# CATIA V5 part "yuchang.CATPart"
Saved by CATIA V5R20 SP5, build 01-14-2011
Part number: yuchang
Material "Iron": density 7870 kg/m3, Young's modulus 2.11e+11 Pa, Poisson ratio 0.291, thermal expansion 1.21e-05 1/K
Material "DS Marble": density 2770 kg/m3, Young's modulus 6e+10 Pa, Poisson ratio 0.27
Material "Dark Oak": density 769 kg/m3, Young's modulus 1.23e+10 Pa
Material "Walnut": density 609 kg/m3, Young's modulus 1.16e+10 Pa
Bounding box of the stored display mesh (mm): x -84.274 to 26, y -5.803 to 5.803, z -3.058 to 3.058
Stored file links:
  F:\yuchang.CATPart
  D:\CATIA V5 R20 WIN64\CATIA V5 R20\win_b64\startup\materials\Catalog.CATMaterial
  D:\CATIA V5 R20 WIN64\CATIA V5 R20\win_b64\startup\materials\dark_oak.jpg
  D:\CATIA V5 R20 WIN64\CATIA V5 R20\win_b64\startup\materials\walnut.jpg
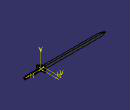
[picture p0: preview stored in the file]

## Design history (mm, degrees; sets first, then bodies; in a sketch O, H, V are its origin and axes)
Body1 (main body), material "Dark Oak"
  Sketch1 on xy-plane, origin (0, 0, 0), H (1, 0, 0), V (0, 1, 0)
    point P1 (4, 0)
    line L1 (4, 0) -> (4, 5.8034)
    point P2 (4, 5.8034)
    arc A1 centre (4.0286, 3.9101) radius 1.8935 from (4, 5.8034) to (2.1616, 4.2259) ccw
    point P4 (2.1616, 4.2259)
    arc A2 centre (2.9922, 1.1934) radius 3.1442 from (2.1616, 4.2259) to (0, 2.1592) ccw
    point P6 (0, 2.1592)
    line L2 (0, 2.1592) -> (-1.8753, 0)
    point P7 (-1.8753, 0)
    axis line L3 (-3.4574, 0) -> (9.2536, 0)
    point P8 (-3.4574, 0)
    point P10 (-1.8753, 0)
    point P11 (0, -2.1592)
    line L4 (0, -2.1592) -> (-1.8753, 0)
    point P12 (2.1616, -4.2259)
    arc A3 centre (2.9922, -1.1934) radius 3.1442 from (2.1616, -4.2259) to (0, -2.1592) cw
    point P14 (4, -5.8034)
    arc A4 centre (4.0286, -3.9101) radius 1.8935 from (4, -5.8034) to (2.1616, -4.2259) cw
    point P16 (4, 0)
    line L5 (4, 0) -> (4, -5.8034)
    distance L1 V = 4
    coincidence: P1 H, P6 V, P8 H, P1 P16, P7 P10
    vertical: L1 V
    tangency: L2 A1
    horizontal: L3 H
    symmetry: P7 P10 L3, P6 P11 L3, L2 L4 L3, P4 P12 L3, A2 A3 L3, P2 P14 L3, A1 A4 L3, P1 P16 L3, L1 L5 L3
  Pad1: profile Sketch1, direction (0, 0, 1), length 2, mirrored extent
  Sketch2 on xy-plane, origin (0, 0, 0), H (1, 0, 0), V (0, 1, 0)
    point P1 (4, 0)
    distance P1 V = 4
    coincidence: P1 H
  Plane1: type Angle, RefPlane xy-plane, Direction Y axis, Angle 90
  Plane2: type Offset, RefPlane Plane1, Offset 4
  Sketch3 on Plane2, origin (4, 0, 0), H (0, 1, 0), V (0, 0, 1)
    axis line L1 (-6.2412, 0) -> (7.4049, 0)
    point P1 (-6.2412, 0)
    coincidence: P1 H
    horizontal: L1 H
  Body2, material "DS Marble"
    Sketch4 on Plane2, origin (4, 0, 0), H (0, 1, 0), V (0, 0, 1)
      arc A1 centre (0, 0) radius 3.2 from (3.2, 0) to (-3.2, 0) ccw
      axis line L1 (-6.2184, 0) -> (7.2498, 0)
      point P1 (-6.2184, 0)
      point P3 (-3.2, 0)
      point P4 (3.2, 0)
      radius A1 = 3.2
      coincidence: P1 H, L1 P3, L1 P4
      horizontal: L1 H
    Shaft1: profile Sketch4, axis Sketch4.L1, angle 180
  Assemble1: tool Body2
Body3, material "Walnut"
  Sketch5 on Plane2, origin (4, 0, 0), H (0, 1, 0), V (0, 0, 1)
    circle A1 centre (0, 0) radius 1.7208
  Pad2: profile Sketch5, direction (1, 0, 0), length 22
  Body4
    Plane3: type Offset, RefPlane xy-plane, Offset 1.2
    Sketch6 on Plane3, origin (0, 0, 1.2), H (1, 0, 0), V (0, 1, 0)
      line L1 (4.0451, 2.1516) -> (23.6416, 2.1516)
      line L2 (23.6416, 2.1516) -> (23.6416, -2.3796)
      line L3 (23.6416, -2.3796) -> (4.0451, -2.3796)
      line L4 (4.0451, -2.3796) -> (4.0451, 2.1516)
      horizontal: L1 H, L3 H
      vertical: L2 V, L4 V
    Pad3: profile Sketch6, direction (0, 0, 1), length 4
    Mirror1: of Pad3, about xy-plane
  Remove1: tool Body4
  Body5
    Sketch7 on face of Pad3 from Sketch6.L4, origin (4.0451, 0, 0), H (0, 1, 0), V (0, 0, 1)
      circle A1 centre (0, 1.216) radius 0.1
      point P1 (0, 1.216)
      radius A1 = 0.1
      coincidence: P1 V
    Pad4: profile Sketch7, direction (1, 0, 0), length 20
    Mirror2: of Pad4, about xy-plane
  Assemble2: tool Body5
Body6, material "Iron"
  Plane4: type Angle, RefPlane xy-plane, Direction X axis, Angle 7.5
  Sketch8 on Plane2, origin (4, 0, 0), H (0, 1, 0), V (0, 0, 1)
    line L1 (-2.9997, 0) -> (0, 0.5)
    point P1 (-2.9997, 0)
    point P2 (0, 0.5)
    line L2 (0, 0.5) -> (2.9997, 0)
    line L3 (2.9997, 0) -> (0, -0.5)
    line L4 (0, -0.5) -> (-2.9997, 0)
    point P3 (2.9997, 0)
    coincidence: P1 H, P2 V, P3 H
    parallelism: L4 L2, L1 L3
  Pad5: profile Sketch8, direction (-1, 0, 0), length 90
  Plane5: type Angle, RefPlane xy-plane, Direction Y axis, Angle -40
  Sketch9 on xy-plane, origin (0, 0, 0), H (1, 0, 0), V (0, 1, 0)
    axis line L1 (-91.9939, 0) -> (33.05, 0)
    point P1 (-91.9939, 0)
    coincidence: P1 H
    horizontal: L1 H
  Body7
    Plane6: type Offset, RefPlane xy-plane, Offset 2
    Plane7: type Angle, RefPlane Plane6, Direction Y axis, Angle -7.5
    Plane8: type Offset, RefPlane Plane7, Offset 11
    Sketch10 on Plane8, origin (-1.4358, 0, 10.9059), H (0, -1, 0), V (0.9914, 0, 0.1305)
      line L1 (-3.9823, -69.945) -> (4.0823, -69.945)
      line L2 (4.0823, -69.945) -> (4.0823, -88.264)
      line L3 (4.0823, -88.264) -> (-3.9823, -88.264)
      line L4 (-3.9823, -88.264) -> (-3.9823, -69.945)
      horizontal: L1 H, L3 H
      vertical: L2 V, L4 V
    Plane9: type Offset, RefPlane xy-plane, Offset 2
    Pad6: profile Sketch10, direction (-0.1305, 0, 0.9914), length 20
    Mirror3: of Pad6, Sketch10, about xy-plane
  Remove2: tool Body7
  Body8
    Sketch11 on xy-plane, origin (0, 0, 0), H (1, 0, 0), V (0, 1, 0)
      point P1 (-76.1106, 3.0504)
      line L1 (-76.1106, 3.0504) -> (-84.9685, 0)
      point P2 (-84.9685, 0)
      line L2 (-84.9685, 0) -> (-84.9685, 3.0504)
      point P3 (-84.9685, 3.0504)
      line L3 (-84.9685, 3.0504) -> (-76.1106, 3.0504)
      reference projected line E1 (4, 0) -> (-80.4764, 0) from edge [face of Pad5 from Sketch8.L2 | face of Pad5 from Sketch8.L1]
      point P6 (-84.9685, 0)
      point P7 (-76.1106, -3.0504)
      line L4 (-76.1106, -3.0504) -> (-84.9685, 0)
      point P8 (-84.9685, -3.0504)
      line L5 (-84.9685, 0) -> (-84.9685, -3.0504)
      line L6 (-84.9685, -3.0504) -> (-76.1106, -3.0504)
      coincidence: P2 H, P2 P6
      vertical: L2 V
      horizontal: L3 H
      symmetry: P2 P6 E1, P1 P7 E1, L1 L4 E1, P3 P8 E1, L2 L5 E1, L3 L6 E1
    Pad7: profile Sketch11, direction (0, 0, 1), length 20, mirrored extent
  Remove3: tool Body8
